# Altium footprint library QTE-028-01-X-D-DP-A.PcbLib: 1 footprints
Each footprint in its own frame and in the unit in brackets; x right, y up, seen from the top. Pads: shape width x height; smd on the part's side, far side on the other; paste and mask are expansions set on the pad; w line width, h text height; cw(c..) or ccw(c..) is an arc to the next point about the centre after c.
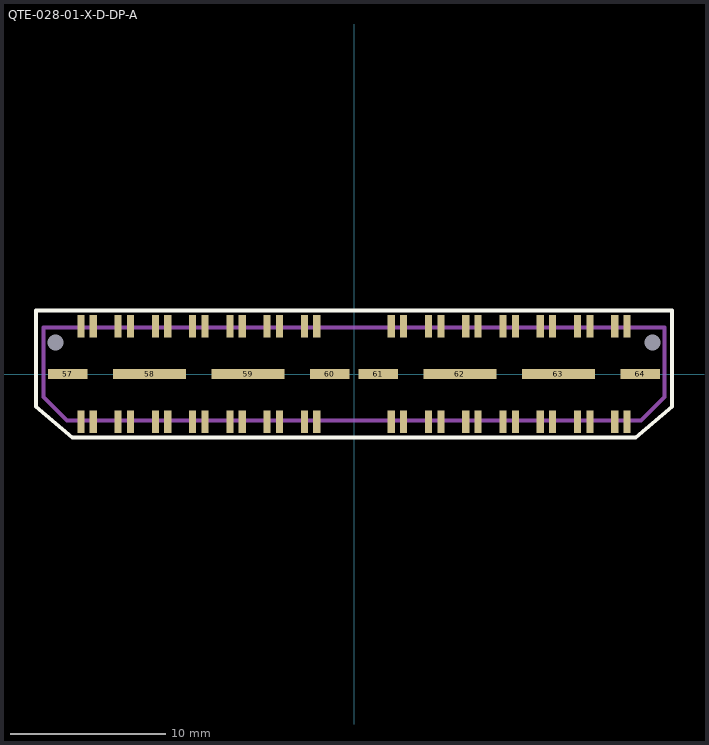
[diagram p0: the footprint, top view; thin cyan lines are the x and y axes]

## QTE-028-01-X-D-DP-A [mm]
pads (66):
  rect 0.46x1.45 smd mask+0.05: 1(-17.6,3.09) 2(-17.6,-3.09) 3(-16.8,3.09) 4(-16.8,-3.09) 5(-15.2,3.09) 6(-15.2,-3.09) 7(-14.4,3.09) 8(-14.4,-3.09) 9(-12.8,3.09) 10(-12.8,-3.09) 11(-12,3.09) 12(-12,-3.09) 13(-10.4,3.09) 14(-10.4,-3.09) 15(-9.6,3.09) 16(-9.6,-3.09) 17(-8,3.09) 18(-8,-3.09) 19(-7.2,3.09) 20(-7.2,-3.09) 21(-5.6,3.09) 22(-5.6,-3.09) 23(-4.8,3.09) 24(-4.8,-3.09) 25(-3.2,3.09) 26(-3.2,-3.09) 27(-2.4,3.09) 28(-2.4,-3.09) 29(2.4,3.09) 30(2.4,-3.09) 31(3.2,3.09) 32(3.2,-3.09) 33(4.8,3.09) 34(4.8,-3.09) 35(5.6,3.09) 36(5.6,-3.09) 37(7.2,3.09) 38(7.2,-3.09) 39(8,3.09) 40(8,-3.09) 41(9.6,3.09) 42(9.6,-3.09) 43(10.4,3.09) 44(10.4,-3.09) 45(12,3.09) 46(12,-3.09) 47(12.8,3.09) 48(12.8,-3.09) 49(14.4,3.09) 50(14.4,-3.09) 51(15.2,3.09) 52(15.2,-3.09) 53(16.8,3.09) 54(16.8,-3.09) 55(17.6,3.09) 56(17.6,-3.09)
  rect 2.54x0.64 smd mask+0.05: 57(-18.445,0) 60(-1.555,0) 61(1.555,0) 64(18.445,0)
  rect 4.7x0.64 smd mask+0.05: 58(-13.175,0) 59(-6.825,0) 62(6.825,0) 63(13.175,0)
  round 0 hole 1.02 unplated: 65(-19.24,2.04) 66(19.24,2.04)
Top Overlay:
  lines w0.254: -20.5,-2.1 -20.5,4.1 20.5,4.1 20.5,-2.1 18.15,-4.1 -18.15,-4.1 -20.5,-2.1
Mechanical 1:
  lines w0.254: -20,-1.485 -20,2.985 20,2.985 20,-1.485 18.5,-2.985 -18.5,-2.985 -20,-1.485
  text "J1" at -0.446,-0.457 h0.76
